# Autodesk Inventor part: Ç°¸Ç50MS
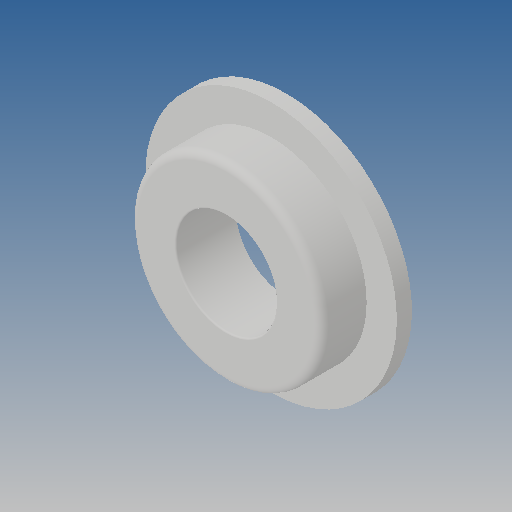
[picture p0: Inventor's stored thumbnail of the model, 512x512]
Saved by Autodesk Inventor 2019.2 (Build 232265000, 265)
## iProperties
Created: 2013-07
Part Number: Ç°¸Ç50MS
Material: Ogólny
Document SubType Name: Modeling
Designer: CADENGINEERING4
Density: 1 g/cm^3
Appearance: Domyślna
Author: CADENGINEERING4
Revision Number: ÈÎºÎ
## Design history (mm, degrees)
feature "ÇÐ³ý-Ðý×ª1"
node "Bryła1"
